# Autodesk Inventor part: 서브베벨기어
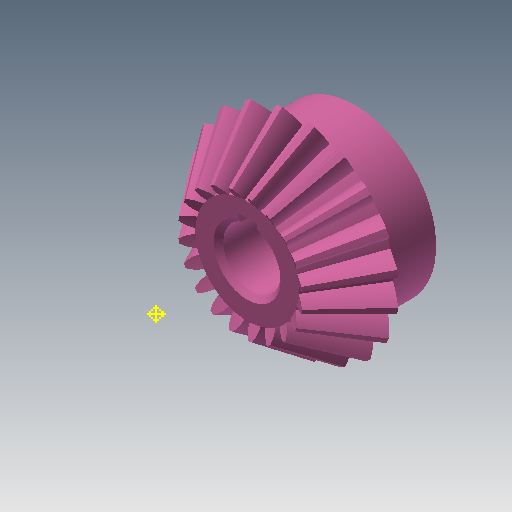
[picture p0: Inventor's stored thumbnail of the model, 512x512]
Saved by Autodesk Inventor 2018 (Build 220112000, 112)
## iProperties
Created: 2018-09
Part Number: 서브베벨기어
Material: 강철, 탄소
Document SubType Name: Modeling
Categories: <?xml version="1.0" encoding="UTF-16"?> <MemberInstance><Categories><FamilyTemplate><FamilyTemplateParameter ValueType="xs:double" Id="1" ObjectReferenceKey="da
Mass: 135.037 g
Surface Area: 63.6444 cm^2
Volume: 17.1585 cm^3
Density: 7.87 g/cm^3
Appearance: 분홍색
CustomPartVersion: 1
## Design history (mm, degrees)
node "맨 위 점"
node "메쉬 평면2"
sketch "톱니 본체 스케치"
  geometry: L1 (0, 0)-(18.003, -31.331); L2 (18.003, -31.331)-(21.664, -28.891); L3 (21.664, -28.891)-(0, 0); L4 (20, -30)-(0, 0); L5 (10.813, -18.818)-(13.012, -17.352); L6 (18.003, -31.331)-(10.813, -18.818); L7 (21.664, -28.891)-(13.012, -17.352); L8 (0, -39.387)-(0, 6.564) reference; L9 (0, -30)-(21.664, -30)
  constraints: 16 end point, 4 point on line, 3 perpendicular, 2 collinear, 1 horizontal alignment, 1 vertical alignment
  dimensions: "d0" = 40 diameter of L4.start L8 (= da_de); "d1" = 36.00616 diameter of L1.end L8 (= da_dfe); "d2" = 43.3282 diameter of L2.end L8 (= da_dae); "d3" = 14.4 distance between parallel lines of L2 L5 (= da_b); "d4" = 28.8906 vertical distance of L2.end L1.start (= da_ve)
revolve "톱니 본체" sketch "톱니 본체 스케치" stored, may be unused: angle "d5" = 90 deg
node "시작점"
node "톱니 평면"
sketch "시작 스케치"
  geometry: L1 (0, -23.505)-(0, 10.645) reference; L2 (-0.834, -2.928)-(0.834, -2.928); A1 r 8.898 centre (-9.698, -3.713) between (-0.834, -2.928) and (-3.903, 3.04); A2 r 8.898 centre (9.698, -3.713) between (3.903, 3.04) and (0.834, -2.928); A3 r 27.357 centre (0, -24.037) between (3.903, 3.04) and (-3.903, 3.04); 1 further point
  constraints: 6 point on circle, 3 centre point, 3 symmetric about line, 2 end point, 1 coincident, 1 perpendicular, 1 other
  dimensions: "d7" = 8.89846 radius of A1 (= fd_rr); "d8" = 9.69794 horizontal distance of point (0, -24.037) A1.centre (= fd_x); "d9" = 20.32439 vertical distance of point (0, -24.037) A1.centre (= fd_y); "d57" = 27.35701 radius of A3 (= 0.5 x fd_dva + 0.3 x da_he); "d58" = 21.10901 distance from line of A3.centre L2 (= 0.5 x fd_dva - 1.12 x da_he)
node "끝점"
  node "끝 평면"
sketch "3D 스케치 오른쪽"
  node "Helical Curve Right" dims "d65" = 229.90621 (computed from da_dm, da_delta, da_beta), "d66" = 31.5, "d67" = 40 (= da_de), "d68" = -5.88003 (= -da_delta), "d69" = 12.16458 (computed from fd_loft, da_delta)
node "끝 평면 오른쪽"
sketch "끝 스케치 오른쪽"
  geometry: L1 (0, -22.649)-(0, 12.15) reference; L2 (-0.497, -1.72)-(0.497, -1.72); A1 r 5.299 centre (-5.775, -2.187) between (-0.497, -1.72) and (-2.324, 1.834); A2 r 5.299 centre (5.775, -2.187) between (2.324, 1.834) and (0.497, -1.72); A3 r 16.291 centre (0, -14.29) between (2.324, 1.834) and (-2.324, 1.834); 1 further point
  constraints: 6 point on circle, 3 centre point, 3 symmetric about line, 2 end point, 1 coincident, 1 perpendicular, 1 other
  dimensions: "d70" = 5.77526 horizontal distance of A3.centre A1.centre (computed from fd_x, fd_ratio); "d71" = 12.10346 vertical distance of point (0, -14.29) A1.centre (computed from fd_y, fd_ratio); "d72" = 5.29916 radius of A1 (computed from fd_rr, fd_ratio); "d73" = 12.57071 distance from line of point (0, -14.29) L2 (computed from d58, fd_ratio); "d74" = 16.29149 radius of A3 (computed from d57, fd_ratio)
feature "로프트 오른쪽" sketch "끝 스케치 오른쪽" dims "d75" = 0, "d77" = 0, "d79" = 0, "d80" = 90 deg, "d85" = 20, "d92" = 90 deg, "d93" = 90 deg, "da_teethtype" = 0 [user parameter]
sketch "3D 스케치 왼쪽"
  node "Helical Curve Left" dims "d26" = 229.90621 (computed from da_dm, da_delta, da_beta), "d27" = 12.16458 (computed from fd_loft, da_delta), "d28" = 40 (= da_de), "d29" = -5.88003 (= -da_delta)
node "끝 평면 왼쪽"
sketch "끝 스케치 왼쪽" dims "d56" = 10.82768 (derived)
  geometry: L1 (0, -35.087)-(0, 18.089) reference; L2 (-0.497, -1.716)-(0.497, -1.716); A1 r 5.299 centre (-5.775, -2.183) between (-0.497, -1.716) and (-2.324, 1.838); A2 r 5.299 centre (5.775, -2.183) between (2.324, 1.838) and (0.497, -1.716); A3 r 16.291 centre (0, -14.287) between (2.324, 1.838) and (-2.324, 1.838); 2 further points; 1 other entity
  constraints: 6 point on circle, 3 centre point, 3 symmetric about line, 2 end point, 1 coincident, 2 other
  dimensions: "d30" = 5.29916 radius of A1 (computed from fd_rr, fd_ratio); "d31" = 5.77526 horizontal distance of point (0, -14.287) A1.centre (computed from fd_x, fd_ratio); "d32" = 12.10346 vertical distance of A1.centre point (0, -14.287) (computed from fd_y, fd_ratio); "d61" = 16.29149 radius of A3 (computed from d57, fd_ratio); "d62" = 12.57071 distance from line of point (0, -14.287) L2 (computed from d58, fd_ratio)
feature "로프트 왼쪽" sketch "끝 스케치 왼쪽" dims "d35" = 0, "d37" = 0, "d39" = 0, "d40" = 90 deg, "d84" = 10, "d90" = 90 deg, "d91" = 90 deg, "da_teethtype" = 0 [user parameter]
sketch "본체 스케치"
  geometry: L1 (0, -35.038)-(0, -19.531) reference; L2 (18.003, -31.331)-(10.813, -18.818) reference; L3 (10.813, -18.818)-(0, -18.818); L4 (18.003, -31.331)-(0, -31.331)
  constraints: 4 end point, 2 perpendicular, 2 point on line
revolve "본체 고정" sketch "본체 스케치" stored, may be unused: angle "d46" = 90 deg
feature "피치 지름" dims angle "d47" = 90 deg
sketch "스케치8"
  geometry: C1 r 17 at (0, 0); 1 further point
  constraints: 1 centre point, 1 coincident
  dimensions: "d94" = 34 diameter of C1
extrude "돌출1" join sketch "스케치8" distance "d95" = 10; taper "d96" = 0 deg
sketch "스케치9"
  geometry: 1 further point
hole "구멍1" sketch "스케치9" at (0, 0) diameter "d97" = 12; stored, may be unused: countersink angle "d101" = 90 deg, drill point angle "d103" = 118 deg; dims "d98" = 6, "d99" = 4, "d100" = 2, "d102" = 8
sketch "스케치10"
  geometry: 1 further point
sketch "스케치11"
  geometry: 1 further point
sketch "스케치12"
  geometry: L1 (-2, 5.657)-(-2, 7.8); L2 (-2, 7.8)-(2, 7.8); L3 (2, 7.8)-(2, 5.657); A1 r 6 centre (0, 0) between (-2, 5.657) and (2, 5.657) reference; 1 further point
  constraints: 6 end point, 2 parallel, 2 point on circle, 1 perpendicular, 1 vertical
  dimensions: "d104" = 4 distance of L1.end L2.end; "d105" = 13.8 dimension on A1 L2
extrude "돌출2" cut sketch "스케치12" extent not by distance; stored distance "d106" = 7; taper "d107" = 0 deg
chamfer "모따기1" distance "d108" = 1; stored, may be unused: second distance "d109" = 2, angle "d110" = 45 deg
body "Solid1"
feature "로프트" dims "d17" = 0, "d18" = 90 deg, "d19" = 0, "d20" = 90 deg, "d89" = 0, "da_teethtype" = 0 [user parameter]
pattern_circular "원형 패턴" dims angle "d22" = 360 deg, "d88" = 0, "da_teethtype" = 0 [user parameter]
pattern_circular "원형 패턴 오른쪽" dims angle "d82" = 360 deg, "da_teethtype" = 0 [user parameter]
pattern_circular "원형 패턴 왼쪽" dims angle "d42" = 360 deg, "da_teethtype" = 0 [user parameter]
sketch "끝 스케치"
  geometry: L1 (0, -15.359)-(0, 6.983) reference; L2 (-0.497, -1.72)-(0.497, -1.72); A1 r 5.299 centre (-5.775, -2.187) between (-0.497, -1.72) and (-2.324, 1.834); A2 r 5.299 centre (5.775, -2.187) between (2.324, 1.834) and (0.497, -1.72); A3 r 16.291 centre (0, -14.29) between (2.324, 1.834) and (-2.324, 1.834); 1 further point
  constraints: 6 point on circle, 3 centre point, 3 symmetric about line, 2 end point, 1 coincident, 1 other
  dimensions: "d12" = 5.29916 radius of A1 (computed from fd_rr, fd_ratio); "d15" = 5.77526 horizontal distance of A1.centre point (0, -14.29) (computed from fd_x, fd_ratio); "d16" = 12.10346 vertical distance of A1.centre point (0, -14.29) (computed from fd_y, fd_ratio); "d59" = 16.29149 radius of A3 (computed from d57, fd_ratio); "d60" = 12.57071 distance from line of A3.centre L2 (computed from d58, fd_ratio)
sketch "Sketch6"
  geometry: L1 (20, -30)-(0, 0) reference; L2 (0, -37.8)-(0, 6.3) reference
body "Srf1"
other parameters: "da_b" = 14.4 [user parameter; used in 2 equation terms], "da_de" = 40 [user parameter; used in 4 equation terms], "da_dae" = 43.3282 [user parameter; used in 2 equation terms], "da_dfe" = 36.00616 [user parameter; used in 1 equation term], "da_le" = 36.05551 [user parameter; used in 1 equation term], "da_omega" = 90 deg [user parameter; used in 1 equation term], "da_beta" = 0 [user parameter; used in 2 equation terms], "da_delta" = 5.88003 [user parameter; used in 8 equation terms], "da_alpha" = 20 deg [user parameter; used in 2 equation terms], "da_he" = 4.4 [user parameter; used in 4 equation terms], "da_ve" = 28.8906 [user parameter; used in 1 equation term], "fd_dv" = 48.07402 (computed from da_de, da_delta) [user parameter; used in 1 equation term], "fd_dva" = 52.07402 (computed from da_dae, da_delta) [user parameter; used in 3 equation terms], "fd_dvb" = 45.1748 (computed from fd_dv, da_alpha) [user parameter; used in 2 equation terms], "da_zv" = 240.37008 [user parameter; used in 1 equation term], "fd_loft" = 14.62 (= da_b + 0.05 x da_he) [user parameter; used in 4 equation terms], "fd_ratio" = 5.95514 (computed from da_le, fd_loft) [user parameter; used in 15 equation terms], "fd_rr" = 8.89846 (computed from fd_dd, fd_dvb) [user parameter; used in 6 equation terms], "fd_angle" = 0.66075 (computed from da_zv) [user parameter; used in 4 equation terms], "fd_x1" = 1.58709 (computed from da_dvw, fd_angle) [user parameter; used in 1 equation term], "fd_y1" = 23.98456 (computed from da_dvw, fd_angle) [user parameter; used in 1 equation term], "fd_x2" = 8.11084 (computed from fd_rr, fd_angle2, fd_angle) [user parameter; used in 1 equation term], "fd_y2" = 3.66016 (computed from fd_rr, fd_angle2, fd_angle) [user parameter; used in 1 equation term], "fd_x" = 9.69794 (= fd_x1 + fd_x2) [user parameter; used in 4 equation terms], "fd_y" = 20.32439 (= fd_y1 - fd_y2) [user parameter; used in 4 equation terms], "fd_angle2" = 3.57832 (computed from fd_dvb, fd_dd, da_alpha) [user parameter; used in 2 equation terms], "fd_dd" = 48.55402 (= fd_dva - 0.8 x da_he) [user parameter; used in 2 equation terms], "da_dvw" = 48.07402 [user parameter; used in 2 equation terms], "d11" = 14.62 (= fd_loft), "da_dm" = 32.01232 [user parameter; used in 2 equation terms], "da_x" = 0 [user parameter], "da_m" = 2 [user parameter], "d48" = 0, "d49" = 0, "d50" = 90 deg (= da_omega), "d51" = 9 deg (computed from da_z), "d52" = 0, "d53" = 0, "d54" = 0
